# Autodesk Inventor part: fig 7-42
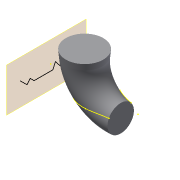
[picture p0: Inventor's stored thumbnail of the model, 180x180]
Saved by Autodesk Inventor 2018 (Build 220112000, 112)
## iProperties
Created: 2011-07
Part Number: fig 7-42
Material: Generic
Document SubType Name: Modeling
Designer: CadCim
Density: 1 g/cm^3
Appearance: Default
Author: CadCim
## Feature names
1. Sweep1
## Parameters: d0 = 5 deg, d1 = -14.75 mm, d2 = 0
